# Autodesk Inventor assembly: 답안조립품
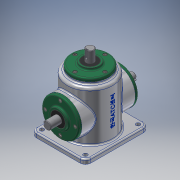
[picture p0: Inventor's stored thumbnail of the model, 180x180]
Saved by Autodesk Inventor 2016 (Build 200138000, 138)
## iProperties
Created: 2021-02
Part Number: 답안조립품
Material: 일반
Document SubType Name: Assembly
Designer: user
Author: user
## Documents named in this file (16)
- C:\Users\user\Desktop\710206V1004\답안조립품.iam
- C:\Users\user\Desktop\710206V1004\본체.ipt
- C:\Users\user\Desktop\710206V1004\메인 베벨기어.ipt
- C:\Users\user\Desktop\710206V1004\메인 축.ipt
- 메인 축.ipt
- C:\Users\user\Desktop\710206V1004\베어링 6203.ipt
- C:\Users\user\Desktop\710206V1004\볼트 M4.ipt
- 볼트 M4.ipt
- C:\Users\user\Desktop\710206V1004\서브 베벨기어.ipt
- C:\Users\user\Desktop\710206V1004\서브 축.ipt
- 서브 축.ipt
- C:\Users\user\Desktop\710206V1004\오일 실.ipt
- 오일 실.ipt
- C:\Users\user\Desktop\710206V1004\커버.ipt
- C:\Users\user\Desktop\710206V1004\키 4x4.ipt
- C:\Users\user\Desktop\710206V1004\키 5x5.ipt
